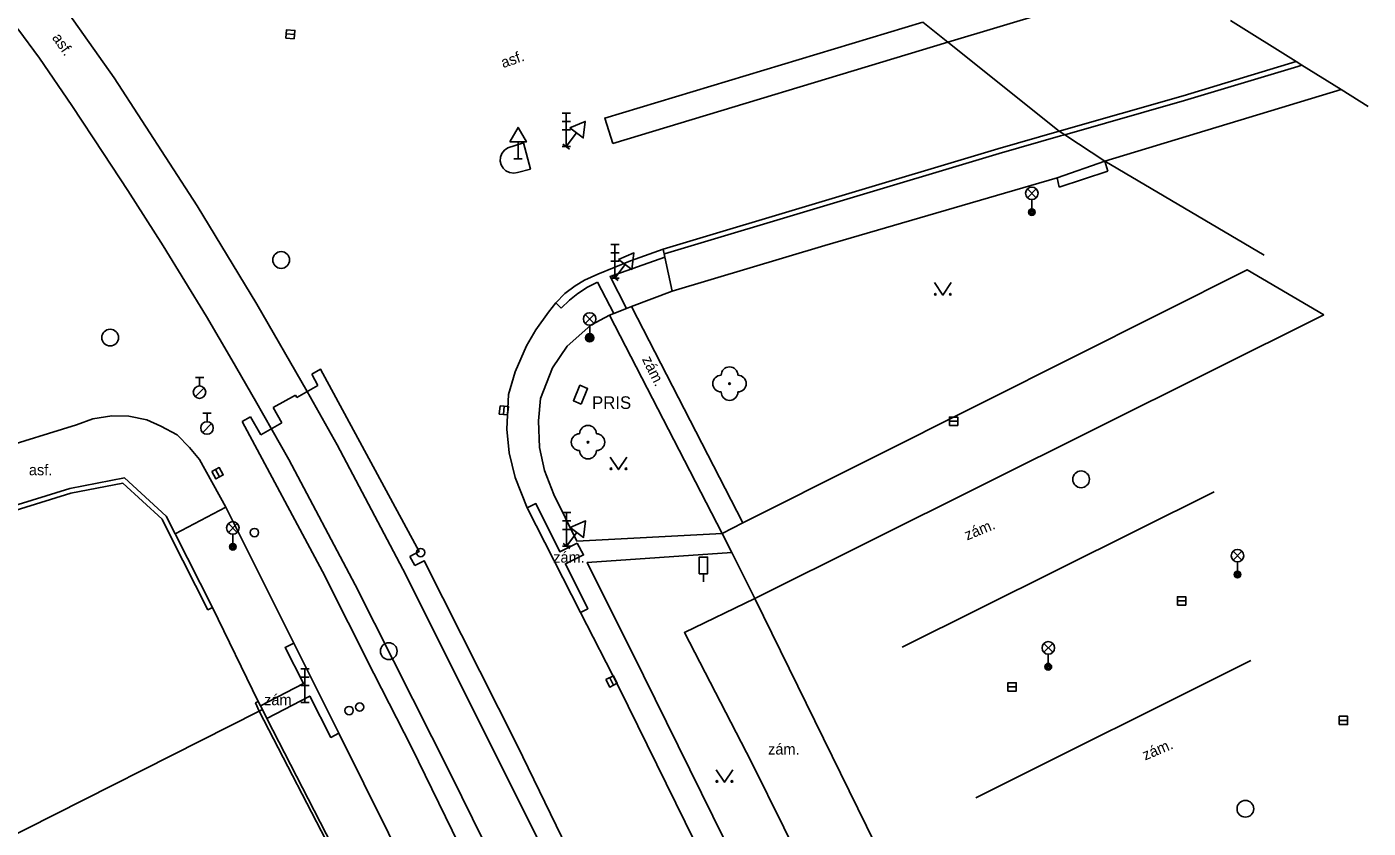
# Model space of a CAD drawing. Extents: x -598341 to -594502, y -1162301 to -1161406.
# Drawn here: x -597440.9 to -597360.7, y -1161748.9 to -1161701 of the extents above; entities that cross this region are included whole.
import ezdxf

# ---------------------------------------------------------------- set-up
doc = ezdxf.new("R2010")
doc.units = 0
for name, color, linetype in [('Vrstva 10', 7, 'Continuous'), ('Vrstva 11', 7, 'Continuous'), ('Vrstva 13', 7, 'Continuous'), ('Vrstva 14', 7, 'Continuous'), ('Vrstva 22', 7, 'Continuous'), ('Vrstva 24', 7, 'Continuous'), ('Vrstva 25', 7, 'Continuous'), ('Vrstva 27', 7, 'Continuous'), ('Vrstva 28', 7, 'Continuous'), ('Vrstva 33', 7, 'Continuous'), ('Vrstva 34', 7, 'Continuous'), ('Vrstva 36', 7, 'Continuous'), ('Vrstva 38', 7, 'Continuous'), ('Vrstva 40', 7, 'Continuous'), ('Vrstva 41', 7, 'Continuous'), ('Vrstva 7', 7, 'Continuous'), ('Vrstva 8', 7, 'Continuous'), ('Vrstva 9', 7, 'Continuous')]:
    doc.layers.add(name, color=color, linetype=linetype)

msp = doc.modelspace()

# ---------------------------------------------------------------- linework, layer by layer
at = {"layer": 'Vrstva 10'}
for p, q in [((-597373.02, -1161698.07), (-597385.82, -1161701.94)), ((-597385.82, -1161701.94), (-597405.85, -1161708)), ((-597371.76, -1161705.14), (-597365, -1161703.1)), ((-597412.13, -1161708.26), (-597411.19, -1161707.95)), ((-597437.9, -1161724.81), (-597478.09, -1161737.31))]:
    msp.add_line(p, q, dxfattribs=at)
for points in [[(-597405.85, -1161708), (-597406.33, -1161706.48), (-597387.31, -1161700.74)], [(-597379.17, -1161707.26), (-597371.76, -1161705.14)], [(-597411.19, -1161707.95), (-597410.77, -1161709.53), (-597411.55, -1161709.73)], [(-597402.84, -1161714.31), (-597382.83, -1161708.31), (-597379.17, -1161707.26)], [(-597411.55, -1161709.73), (-597411.77, -1161709.77), (-597412.02, -1161709.74), (-597412.24, -1161709.63), (-597412.4, -1161709.47), (-597412.52, -1161709.27), (-597412.58, -1161709.05), (-597412.56, -1161708.81), (-597412.48, -1161708.59), (-597412.32, -1161708.39), (-597412.13, -1161708.26)], [(-597409.25, -1161717.52), (-597408.71, -1161716.97), (-597408.1, -1161716.51), (-597407.53, -1161716.16), (-597406.74, -1161715.8), (-597404.8, -1161715.02), (-597402.84, -1161714.31)], [(-597398.08, -1161730.68), (-597383.66, -1161723.43), (-597367.94, -1161715.54), (-597363.35, -1161718.24)], [(-597410.97, -1161729.78), (-597411.69, -1161727.97), (-597412.04, -1161726.48), (-597412.18, -1161725.08), (-597412.08, -1161723.01), (-597411.69, -1161721.65), (-597411, -1161720.09), (-597410.44, -1161719.13), (-597409.7, -1161718.07), (-597409.25, -1161717.52)], [(-597430.56, -1161726.89), (-597431.15, -1161726.16), (-597431.89, -1161725.42), (-597432.86, -1161724.89), (-597433.69, -1161724.52), (-597434.78, -1161724.29), (-597435.79, -1161724.28), (-597436.92, -1161724.45), (-597437.9, -1161724.81)], [(-597430.56, -1161726.89), (-597428.97, -1161729.74)], [(-597428.97, -1161729.74), (-597424.92, -1161737.86)], [(-597407.78, -1161736.02), (-597410.97, -1161729.78)], [(-597399.31, -1161731.3), (-597398.08, -1161730.68)], [(-597398.74, -1161732.44), (-597399.31, -1161731.3)], [(-597397.36, -1161735.2), (-597398.74, -1161732.44)], [(-597389.67, -1161750.87), (-597393.69, -1161752.79), (-597397.56, -1161744.97), (-597401.57, -1161737.23), (-597397.36, -1161735.2)], [(-597371.42, -1161809.44), (-597376.52, -1161799.05), (-597381.99, -1161788.02), (-597390.76, -1161770.46), (-597405.49, -1161740.5), (-597407.78, -1161736.02)], [(-597424.92, -1161737.86), (-597422.22, -1161743.25)], [(-597422.22, -1161743.25), (-597413.3, -1161761.21)]]:
    msp.add_lwpolyline(points, dxfattribs=at)
at = {"layer": 'Vrstva 11'}
for p, q in [((-597376.44, -1161709.05), (-597362.31, -1161704.78)), ((-597379.29, -1161710.06), (-597376.44, -1161709.05)), ((-597376.26, -1161709.66), (-597376.44, -1161709.05)), ((-597379.16, -1161710.61), (-597379.29, -1161710.06)), ((-597379.16, -1161710.61), (-597376.26, -1161709.66)), ((-597405.79, -1161718.16), (-597406.76, -1161716.29)), ((-597409.25, -1161717.52), (-597408.94, -1161717.85)), ((-597406.04, -1161718.25), (-597405.79, -1161718.16)), ((-597405.03, -1161717.86), (-597405.79, -1161718.16)), ((-597405.03, -1161717.86), (-597404.73, -1161717.75)), ((-597424.74, -1161723.18), (-597423.47, -1161722.46)), ((-597423.47, -1161722.46), (-597423.84, -1161721.79)), ((-597426.14, -1161723.77), (-597424.81, -1161723.04)), ((-597424.81, -1161723.04), (-597424.74, -1161723.18)), ((-597425.62, -1161724.69), (-597426.14, -1161723.77)), ((-597427.5, -1161724.33), (-597426.89, -1161725.41)), ((-597426.89, -1161725.41), (-597425.62, -1161724.69)), ((-597369.91, -1161728.81), (-597388.56, -1161738.11)), ((-597428.97, -1161729.74), (-597432.01, -1161731.32)), ((-597417.98, -1161732.68), (-597417.69, -1161733.22)), ((-597367.71, -1161738.89), (-597384.15, -1161747.1)), ((-597444.51, -1161750.78), (-597426.99, -1161741.92)), ((-597426.99, -1161741.92), (-597426.79, -1161741.82))]:
    msp.add_line(p, q, dxfattribs=at)
for points in [[(-597402.29, -1161716.82), (-597393.17, -1161714.1), (-597379.29, -1161710.06)], [(-597402.84, -1161714.31), (-597402.73, -1161714.79)], [(-597402.73, -1161714.79), (-597406.01, -1161715.95), (-597405.03, -1161717.86)], [(-597402.73, -1161714.79), (-597402.29, -1161716.82)], [(-597408.94, -1161717.85), (-597408.44, -1161717.37), (-597407.93, -1161716.96), (-597407.36, -1161716.59), (-597406.76, -1161716.29)], [(-597404.73, -1161717.75), (-597402.29, -1161716.82)], [(-597409.38, -1161728.97), (-597409.94, -1161727.55), (-597410.22, -1161726.16), (-597410.29, -1161724.57), (-597410.16, -1161723.23), (-597409.45, -1161721.4), (-597408.57, -1161720.11), (-597407.16, -1161718.86), (-597406.04, -1161718.25)], [(-597406.04, -1161718.25), (-597399.31, -1161731.3)], [(-597398.08, -1161730.68), (-597404.73, -1161717.75)], [(-597397.36, -1161735.2), (-597363.35, -1161718.24)], [(-597417.98, -1161732.68), (-597417.43, -1161732.39), (-597423.32, -1161721.48), (-597423.84, -1161721.79)], [(-597427.5, -1161724.33), (-597428.01, -1161724.62)], [(-597375.36, -1161830.11), (-597380.56, -1161819.58), (-597384.65, -1161811.14), (-597402.07, -1161775.92), (-597412.64, -1161754.81), (-597417.86, -1161744.11), (-597420.13, -1161739.67), (-597423.19, -1161733.58), (-597428.01, -1161724.62)], [(-597410.97, -1161729.78), (-597410.44, -1161729.52), (-597409.02, -1161732.4), (-597407.97, -1161731.89)], [(-597408, -1161731.76), (-597409.38, -1161728.97)], [(-597407.97, -1161731.89), (-597407.59, -1161732.59), (-597408.68, -1161733.12), (-597407.35, -1161735.81), (-597407.78, -1161736.02)], [(-597399.31, -1161731.3), (-597408, -1161731.76)], [(-597390.5, -1161766.98), (-597394.33, -1161759.43), (-597404.02, -1161739.8), (-597407.38, -1161733.04), (-597398.74, -1161732.44)], [(-597370.66, -1161825.04), (-597374.47, -1161817.36), (-597384.67, -1161796.76), (-597385.3, -1161797.08), (-597386.12, -1161795.44), (-597385.49, -1161795.12), (-597387.58, -1161790.72), (-597393.28, -1161779.09), (-597394.01, -1161779.46), (-597396.71, -1161773.85), (-597401.38, -1161764.71), (-597407.57, -1161752.16), (-597411.57, -1161743.95), (-597417.12, -1161732.94), (-597417.69, -1161733.22)], [(-597389.67, -1161750.87), (-597397.36, -1161735.2)], [(-597424.92, -1161737.86), (-597425.44, -1161738.12), (-597424.34, -1161740.28), (-597426.9, -1161741.61)], [(-597422.22, -1161743.25), (-597422.7, -1161743.5), (-597423.96, -1161741.03), (-597426.52, -1161742.36)]]:
    msp.add_lwpolyline(points, dxfattribs=at)
at = {"layer": 'Vrstva 13'}
for points in [[(-597470.38, -1161668.8), (-597467.36, -1161670.94), (-597464.35, -1161673.04), (-597461.12, -1161675.62), (-597458.26, -1161678.06), (-597455.83, -1161680.23), (-597452.69, -1161683.22), (-597449.69, -1161686.37), (-597447.17, -1161689.18), (-597444.05, -1161692.84), (-597441, -1161696.66), (-597438.41, -1161700.18), (-597435.66, -1161704.08), (-597430.7, -1161711.73), (-597427.13, -1161717.6), (-597424.11, -1161722.82), (-597422.33, -1161726)], [(-597441.4, -1161701.14), (-597440.12, -1161702.89), (-597438.18, -1161705.73), (-597436.28, -1161708.59), (-597434.83, -1161710.8), (-597432.73, -1161714.11), (-597430.13, -1161718.33), (-597428.62, -1161720.92), (-597427.2, -1161723.37), (-597425.21, -1161726.89)], [(-597372.12, -1161826.62), (-597376.34, -1161818.13), (-597388.64, -1161793.42), (-597398.12, -1161774.25), (-597409.67, -1161750.87), (-597418.39, -1161733.44), (-597422.33, -1161726)], [(-597425.21, -1161726.89), (-597421.25, -1161734.37), (-597415.51, -1161745.76), (-597412.33, -1161752.23), (-597400.82, -1161775.37), (-597383.06, -1161811.47), (-597379.23, -1161819.14), (-597374.33, -1161829)]]:
    msp.add_lwpolyline(points, dxfattribs=at)
at = {"layer": 'Vrstva 14'}
for p, q in [((-597368.92, -1161700.64), (-597365, -1161703.1)), ((-597365, -1161703.1), (-597364.66, -1161703.31)), ((-597364.66, -1161703.31), (-597362.31, -1161704.78)), ((-597362.31, -1161704.78), (-597360.7, -1161705.79)), ((-597376.44, -1161709.05), (-597366.92, -1161714.68))]:
    msp.add_line(p, q, dxfattribs=at)
for points in [[(-597385.82, -1161701.94), (-597387.31, -1161700.74)], [(-597379.17, -1161707.26), (-597385.82, -1161701.94)], [(-597378.84, -1161707.48), (-597379.17, -1161707.26)], [(-597376.44, -1161709.05), (-597378.84, -1161707.48)]]:
    msp.add_lwpolyline(points, dxfattribs=at)
at = {"layer": 'Vrstva 22'}
for centre in [(-597398.87, -1161722.35), (-597407.33, -1161725.85)]:
    msp.add_circle(centre, 0.05, dxfattribs=at)
for centre, start, end in [((-597398.87, -1161721.85), 0, 180), ((-597399.37, -1161722.35), 90, 270), ((-597398.37, -1161722.35), 270, 90), ((-597398.87, -1161722.85), 180, 0), ((-597407.33, -1161725.35), 0, 180), ((-597407.83, -1161725.85), 90, 270), ((-597406.83, -1161725.85), 270, 90), ((-597407.33, -1161726.35), 180, 0)]:
    msp.add_arc(centre, 0.5, start, end, dxfattribs=at)
at = {"layer": 'Vrstva 24'}
msp.add_lwpolyline([(-597407.748, -1161723.569), (-597407.352, -1161722.65), (-597407.811, -1161722.452), (-597408.207, -1161723.371)], close=True, dxfattribs=at)
at = {"layer": 'Vrstva 25'}
for radius in [0.25, 0.2, 0.15, 0.1, 0.05]:
    msp.add_circle((-597407.23, -1161719.61), radius, dxfattribs=at)
at = {"layer": 'Vrstva 27'}
for p, q in [((-597425.369, -1161701.447), (-597424.872, -1161701.493)), ((-597412.337, -1161723.691), (-597412.383, -1161724.189)), ((-597385.73, -1161724.6), (-597385.23, -1161724.6)), ((-597429.589, -1161727.49), (-597429.351, -1161727.93)), ((-597372.1, -1161735.34), (-597371.6, -1161735.34)), ((-597406.031, -1161739.926), (-597405.809, -1161740.374)), ((-597382.23, -1161740.48), (-597381.73, -1161740.48)), ((-597362.43, -1161742.48), (-597361.93, -1161742.48))]:
    msp.add_line(p, q, dxfattribs=at)
for points in [[(-597425.392, -1161701.696), (-597424.894, -1161701.741), (-597424.849, -1161701.244), (-597425.346, -1161701.198)], [(-597412.586, -1161723.668), (-597412.632, -1161724.166), (-597412.134, -1161724.213), (-597412.088, -1161723.714)], [(-597385.73, -1161724.85), (-597385.23, -1161724.85), (-597385.23, -1161724.35), (-597385.73, -1161724.35)], [(-597429.809, -1161727.609), (-597429.571, -1161728.049), (-597429.131, -1161727.811), (-597429.369, -1161727.371)], [(-597372.1, -1161735.59), (-597371.6, -1161735.59), (-597371.6, -1161735.09), (-597372.1, -1161735.09)], [(-597406.255, -1161740.037), (-597406.033, -1161740.485), (-597405.585, -1161740.263), (-597405.807, -1161739.815)], [(-597382.23, -1161740.73), (-597381.73, -1161740.73), (-597381.73, -1161740.23), (-597382.23, -1161740.23)], [(-597362.43, -1161742.73), (-597361.93, -1161742.73), (-597361.93, -1161742.23), (-597362.43, -1161742.23)]]:
    msp.add_lwpolyline(points, close=True, dxfattribs=at)
for centre in [(-597425.67, -1161714.96), (-597435.89, -1161719.6), (-597377.86, -1161728.07), (-597419.24, -1161738.34), (-597368.04, -1161747.76)]:
    msp.add_circle(centre, 0.5, dxfattribs=at)
at = {"layer": 'Vrstva 28'}
for p, q in [((-597430.8, -1161721.985), (-597430.3, -1161721.985)), ((-597430.55, -1161722.485), (-597430.55, -1161721.985)), ((-597430.808, -1161723.132), (-597430.278, -1161722.602)), ((-597430.358, -1161725.272), (-597429.828, -1161724.742)), ((-597430.35, -1161724.125), (-597429.85, -1161724.125)), ((-597430.1, -1161724.625), (-597430.1, -1161724.125))]:
    msp.add_line(p, q, dxfattribs=at)
for centre, radius in [((-597430.55, -1161722.86), 0.375), ((-597430.1, -1161725), 0.375), ((-597427.27, -1161731.25), 0.25), ((-597417.33, -1161732.45), 0.25), ((-597421.61, -1161741.89), 0.25), ((-597420.98, -1161741.68), 0.25)]:
    msp.add_circle(centre, radius, dxfattribs=at)
at = {"layer": 'Vrstva 33'}
for p, q in [((-597408.88, -1161706.18), (-597408.38, -1161706.18)), ((-597408.63, -1161708.18), (-597408.63, -1161706.18)), ((-597408.88, -1161706.68), (-597408.38, -1161706.68)), ((-597408.88, -1161707.18), (-597408.38, -1161707.18)), ((-597408.88, -1161708.18), (-597408.38, -1161708.18)), ((-597381.065, -1161711.24), (-597380.535, -1161710.71)), ((-597381.065, -1161710.71), (-597380.535, -1161711.24)), ((-597380.8, -1161711.35), (-597380.8, -1161712.1)), ((-597405.97, -1161714.04), (-597405.47, -1161714.04)), ((-597405.72, -1161716.04), (-597405.72, -1161714.04)), ((-597405.97, -1161714.54), (-597405.47, -1161714.54)), ((-597405.97, -1161715.04), (-597405.47, -1161715.04)), ((-597405.97, -1161716.04), (-597405.47, -1161716.04)), ((-597407.495, -1161718.75), (-597406.965, -1161718.22)), ((-597407.495, -1161718.22), (-597406.965, -1161718.75)), ((-597407.23, -1161718.86), (-597407.23, -1161719.61)), ((-597408.86, -1161730.06), (-597408.36, -1161730.06)), ((-597408.61, -1161732.06), (-597408.61, -1161730.06)), ((-597428.825, -1161731.24), (-597428.295, -1161730.71)), ((-597428.825, -1161730.71), (-597428.295, -1161731.24)), ((-597408.86, -1161730.56), (-597408.36, -1161730.56)), ((-597408.86, -1161731.06), (-597408.36, -1161731.06)), ((-597428.56, -1161731.35), (-597428.56, -1161732.1)), ((-597408.86, -1161732.06), (-597408.36, -1161732.06)), ((-597368.775, -1161732.9), (-597368.245, -1161732.37)), ((-597368.775, -1161732.37), (-597368.245, -1161732.9)), ((-597368.51, -1161733.01), (-597368.51, -1161733.76)), ((-597380.085, -1161738.41), (-597379.555, -1161737.88)), ((-597380.085, -1161737.88), (-597379.555, -1161738.41)), ((-597379.82, -1161738.52), (-597379.82, -1161739.27)), ((-597424.5, -1161739.4), (-597424, -1161739.4)), ((-597424.5, -1161739.9), (-597424, -1161739.9)), ((-597424.25, -1161741.4), (-597424.25, -1161739.4)), ((-597424.5, -1161740.4), (-597424, -1161740.4)), ((-597424.5, -1161741.4), (-597424, -1161741.4))]:
    msp.add_line(p, q, dxfattribs=at)
for centre, radius in [((-597380.8, -1161710.975), 0.375), ((-597380.8, -1161712.1), 0.2), ((-597380.8, -1161712.1), 0.145), ((-597380.8, -1161712.1), 0.0876), ((-597407.23, -1161718.485), 0.375), ((-597407.23, -1161719.61), 0.2), ((-597407.23, -1161719.61), 0.145), ((-597407.23, -1161719.61), 0.0876), ((-597428.56, -1161730.975), 0.375), ((-597428.56, -1161732.1), 0.2), ((-597428.56, -1161732.1), 0.145), ((-597428.56, -1161732.1), 0.0876), ((-597368.51, -1161732.635), 0.375), ((-597368.51, -1161733.76), 0.2), ((-597368.51, -1161733.76), 0.145), ((-597368.51, -1161733.76), 0.0876), ((-597379.82, -1161738.145), 0.375), ((-597379.82, -1161739.27), 0.2), ((-597379.82, -1161739.27), 0.145), ((-597379.82, -1161739.27), 0.0876)]:
    msp.add_circle(centre, radius, dxfattribs=at)
at = {"layer": 'Vrstva 34'}
for p, q in [((-597411.51, -1161707.902), (-597411.51, -1161708.92)), ((-597408.83, -1161708.03), (-597408.43, -1161708.33)), ((-597408.018, -1161707.367), (-597408.63, -1161708.18)), ((-597411.76, -1161708.92), (-597411.26, -1161708.92)), ((-597405.108, -1161715.227), (-597405.72, -1161716.04)), ((-597405.92, -1161715.89), (-597405.52, -1161716.19)), ((-597407.998, -1161731.247), (-597408.61, -1161732.06)), ((-597408.81, -1161731.91), (-597408.41, -1161732.21))]:
    msp.add_line(p, q, dxfattribs=at)
for points in [[(-597412.01, -1161707.902), (-597411.01, -1161707.902), (-597411.51, -1161707.036)], [(-597408.417, -1161707.066), (-597407.618, -1161707.667), (-597407.497, -1161706.675)], [(-597405.507, -1161714.926), (-597404.708, -1161715.527), (-597404.587, -1161714.535)], [(-597408.397, -1161730.946), (-597407.598, -1161731.547), (-597407.477, -1161730.555)]]:
    msp.add_lwpolyline(points, close=True, dxfattribs=at)
at = {"layer": 'Vrstva 36'}
for points in [[(-597386.62, -1161716.31), (-597386.12, -1161717.06), (-597385.62, -1161716.31)], [(-597406.01, -1161726.74), (-597405.51, -1161727.49), (-597405.01, -1161726.74)], [(-597399.68, -1161745.43), (-597399.18, -1161746.18), (-597398.68, -1161745.43)]]:
    msp.add_lwpolyline(points, dxfattribs=at)
for centre in [(-597386.57, -1161717.01), (-597385.671, -1161717.01), (-597405.96, -1161727.44), (-597405.061, -1161727.44), (-597399.63, -1161746.13), (-597398.731, -1161746.13)]:
    msp.add_circle(centre, 0.05, dxfattribs=at)
at = {"layer": 'Vrstva 38'}
msp.add_line((-597400.43, -1161733.715), (-597400.43, -1161734.2), dxfattribs=at)
msp.add_lwpolyline([(-597400.68, -1161733.715), (-597400.18, -1161733.715), (-597400.18, -1161732.715), (-597400.68, -1161732.715)], close=True, dxfattribs=at)
at = {"layer": 'Vrstva 7'}
msp.add_line((-597426.99, -1161741.92), (-597418.86, -1161757.59), dxfattribs=at)
for points in [[(-597461.13, -1161735.97), (-597446.74, -1161731.22), (-597438.31, -1161728.61), (-597435.04, -1161727.98)], [(-597435.04, -1161727.98), (-597432.54, -1161730.28), (-597432.01, -1161731.32)], [(-597461.01, -1161736.25), (-597446.65, -1161731.5), (-597438.24, -1161728.9), (-597435.13, -1161728.3)], [(-597435.13, -1161728.3), (-597432.78, -1161730.46), (-597432.28, -1161731.46), (-597430.05, -1161735.87), (-597429.78, -1161735.74)], [(-597432.01, -1161731.32), (-597429.78, -1161735.74)], [(-597427.04, -1161741.34), (-597427.2, -1161741.43), (-597426.99, -1161741.92)], [(-597427.04, -1161741.34), (-597426.9, -1161741.61)], [(-597426.9, -1161741.61), (-597426.79, -1161741.82)], [(-597426.79, -1161741.82), (-597426.52, -1161742.36)], [(-597426.52, -1161742.36), (-597418.74, -1161757.5), (-597418.86, -1161757.59)]]:
    msp.add_lwpolyline(points, dxfattribs=at)
at = {"layer": 'Vrstva 8'}
msp.add_line((-597427.04, -1161741.34), (-597429.78, -1161735.74), dxfattribs=at)
at = {"layer": 'Vrstva 9'}
msp.add_line((-597371.68, -1161705.43), (-597364.91, -1161703.39), dxfattribs=at)
for points in [[(-597364.91, -1161703.39), (-597364.66, -1161703.31)], [(-597378.84, -1161707.48), (-597371.68, -1161705.43)], [(-597402.75, -1161714.6), (-597382.75, -1161708.6), (-597379.09, -1161707.55), (-597378.84, -1161707.48)]]:
    msp.add_lwpolyline(points, dxfattribs=at)

# ---------------------------------------------------------------- texts
at = {"layer": 'Vrstva 40'}
for s, height, rotation, p in [('asf.', 0.65, 305.00241, (-597439.39, -1161701.68)), ('asf.', 0.6499, 19.44134, (-597412.4, -1161703.5)), ('zám.', 0.65, 296.24437, (-597404.12, -1161720.89)), ('zám.', 0.65, 22.55872, (-597384.67, -1161731.73)), ('zám.', 0.65, 22.97004, (-597374.03, -1161744.88))]:
    msp.add_text(s, height=height, rotation=rotation, dxfattribs=at).set_placement(p)
for s, p in [('asf.', (-597440.75, -1161727.83)), ('zám.', (-597409.41, -1161733.05)), ('zám.', (-597426.69, -1161741.57)), ('zám.', (-597396.57, -1161744.52))]:
    msp.add_text(s, height=0.65, dxfattribs=at).set_placement(p)
at = {"layer": 'Vrstva 41'}
msp.add_text('PRIS', height=0.75, dxfattribs=at).set_placement((-597407.09, -1161723.86))

doc.saveas('drawing.dxf')
